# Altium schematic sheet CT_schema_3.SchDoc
size 461 x 327 mm
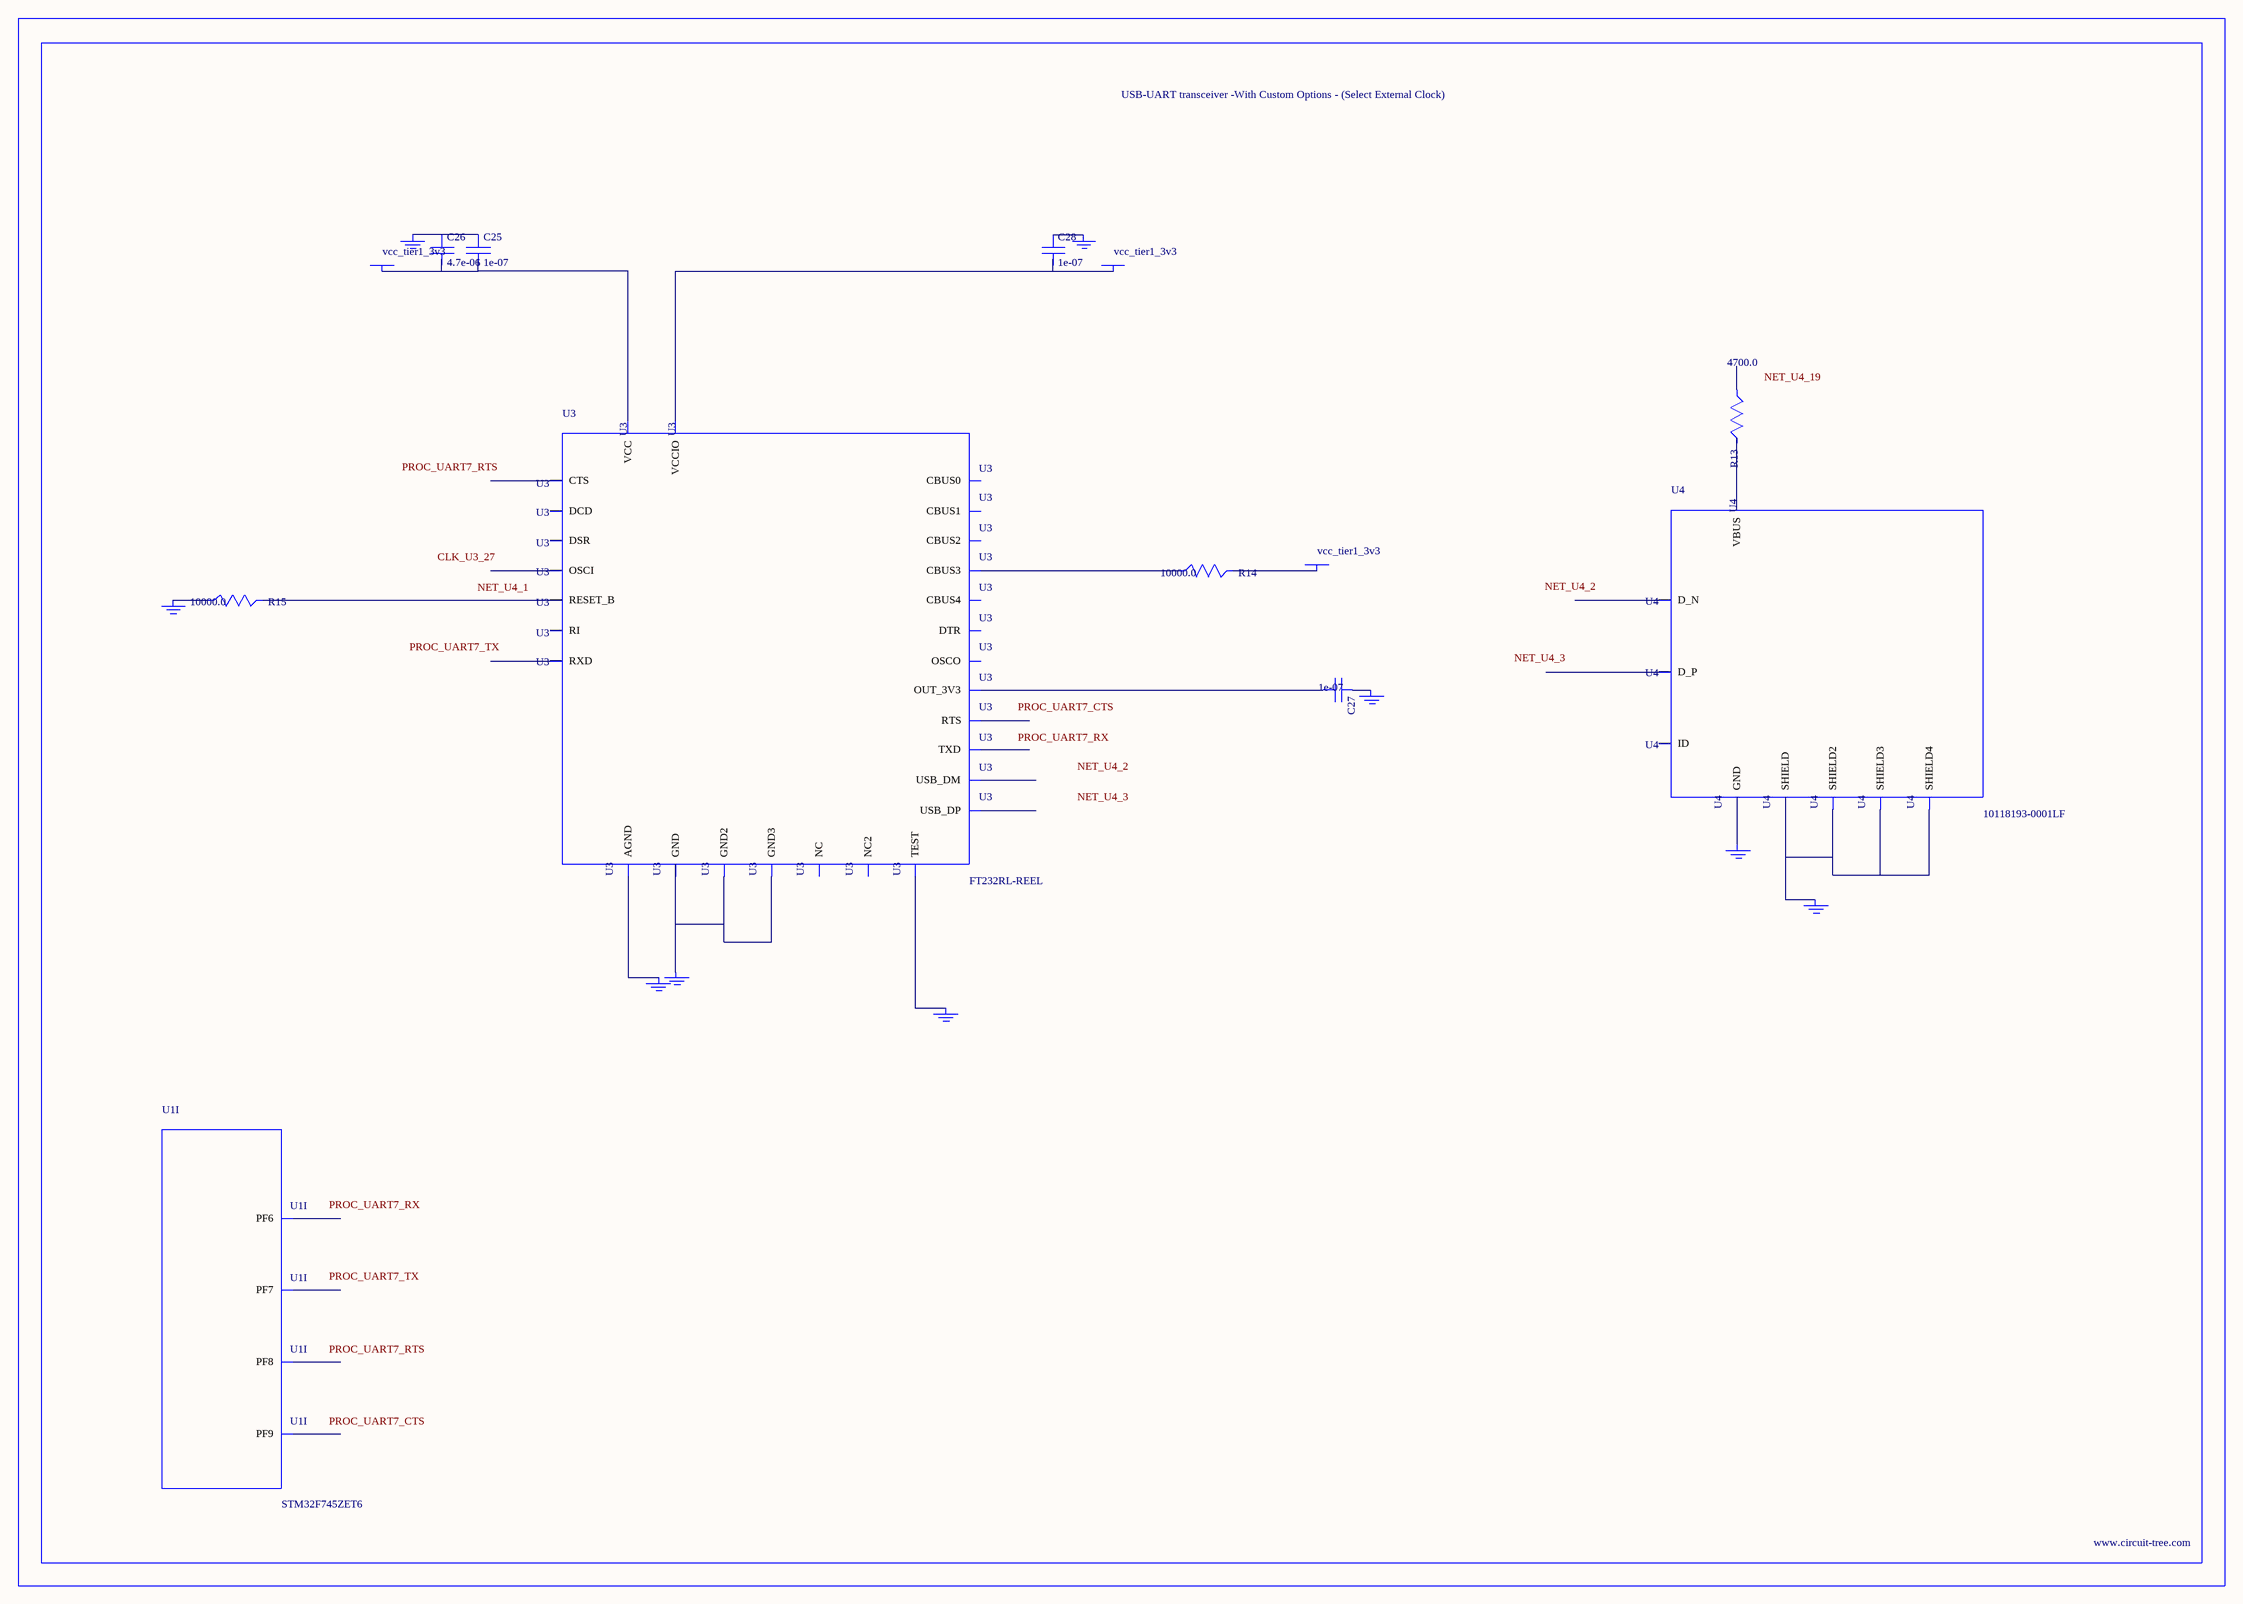
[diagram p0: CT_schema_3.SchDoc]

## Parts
BORDER2  (no value)
C25  1e-07  [C0402]
C26  4.7e-06  [C0805]
C27  1e-07  [C0402]
C28  1e-07  [C0402]
GND_INSTANCE_2_0  (no value)
GND_INSTANCE_2_1  (no value)
GND_INSTANCE_2_2  (no value)
GND_INSTANCE_2_3  (no value)
GND_INSTANCE_2_4  (no value)
GND_INSTANCE_2_5  (no value)
GND_INSTANCE_2_6  (no value)
GND_INSTANCE_2_7  (no value)
GND_INSTANCE_2_8  (no value)
POWER_INSTANCE_2_0  vcc_tier1_3v3
POWER_INSTANCE_2_1  vcc_tier1_3v3
POWER_INSTANCE_2_2  vcc_tier1_3v3
R13  4700.0  [R0603]
R14  10000.0  [R0603]
R15  10000.0  [R0603]
U1  STM32F745ZET6  [LQFP144]  (part I of 12)
U3  FT232RL-REEL  [SSOP-28]
U4  10118193-0001LF  [FCI_10118193-0001LF]

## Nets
NetC25_1: C25.1 C26.1 GND_INSTANCE_2_3.0(GND)
NetC25_2: C25.2 C26.2 POWER_INSTANCE_2_2.0(PWR) U3.20(VCC)
NetC27_1: C27.1 GND_INSTANCE_2_1.0(GND)
NetC27_2: C27.2 U3.17(OUT_3V3)
NetC28_1: C28.1 GND_INSTANCE_2_0.0(GND)
NetC28_2: C28.2 POWER_INSTANCE_2_0.0(PWR) U3.4(VCCIO)
NetGND_INSTANCE_2_2_0: GND_INSTANCE_2_2.0(GND) R15.1
NetGND_INSTANCE_2_4_0: GND_INSTANCE_2_4.0(GND) U3.25(AGND)
NetGND_INSTANCE_2_5_0: GND_INSTANCE_2_5.0(GND) U3.26(TEST)
NetGND_INSTANCE_2_6_0: GND_INSTANCE_2_6.0(GND) U3.7(GND) U3.18(GND2) U3.21(GND3)
NetGND_INSTANCE_2_7_0: GND_INSTANCE_2_7.0(GND) U4.6(SHIELD) U4.7(SHIELD2) U4.8(SHIELD3) U4.9(SHIELD4)
NetGND_INSTANCE_2_8_0: GND_INSTANCE_2_8.0(GND) U4.5(GND)
NetPOWER_INSTANCE_2_1_0: POWER_INSTANCE_2_1.0(PWR) R14.2
NetR13_2: R13.2 U4.1(VBUS)
NetR14_1: R14.1 U3.14(CBUS3)
NetR15_2: R15.2 U3.19(RESET_B)

Not connected (* = marked no-connect by the designer): R13 1; U1 18(PF6) 19(PF7) 20(PF8) 21(PF9); U3 1(TXD) 2(DTR) 3(RTS) 5(RXD) 6(RI) 8(NC) 9(DSR) 10(DCD) 11(CTS) 12(CBUS4) 13(CBUS2) 15(USB_DP) 16(USB_DM) 22(CBUS1) 23(CBUS0) 24(NC2) 27(OSCI) 28(OSCO); U4 2(D_N) 3(D_P) 4(ID)

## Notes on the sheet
- Labels drawn without touching a wire or pin: CLK_U3_27, NET_U4_1, NET_U4_2, NET_U4_3, NET_U4_19, PROC_UART7_CTS, PROC_UART7_RTS, PROC_UART7_RX, PROC_UART7_TX

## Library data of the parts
BORDER2 = BORDER_PAGE2
C25 C27 C28 = C0402C104K3RACTU
C26 = C0805C475K4RACTU
GND_INSTANCE_2_0-GND_INSTANCE_2_8 = GND
POWER_INSTANCE_2_0-POWER_INSTANCE_2_2 = PWR
R13 = RC0603JR-074K7L
R14 R15 = RC0603JR-0710KL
